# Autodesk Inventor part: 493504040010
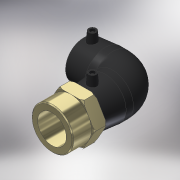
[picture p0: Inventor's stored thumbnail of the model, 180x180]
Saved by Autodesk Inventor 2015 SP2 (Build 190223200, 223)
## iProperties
Created: 2017-06
Part Number: 493504040010
Material: Generic
Description: PLASSON 90° ELBOW FEMALE TRANSITION 40-1''
Document SubType Name: Modeling
Designer: KIM
Mass: 218.635 g
Surface Area: 504.52 cm^2
Volume: 218.635 cm^3
Density: 1 g/cm^3
Appearance: Rubber - Black
Author: KIM
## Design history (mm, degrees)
derived "493504.ipt"
feature "Solid1::493504.ipt"
tag "TaggingFeature1"
body "Solid1"
other parameters: "d2" = 56, "d4" = 30.66667, "d5" = 50.4, "d8" = 168 deg, "d10" = 17.6, "d11" = 5.86667, "d29" = 47, "d30" = 15, "d31" = 50.6, "d34" = 5 deg, "d41" = 4, "d42" = 14, "d43" = 0, "d48" = 64, "d50" = 34, "d51" = 17.6, "d52" = 44, "d54" = 90 deg, "d58" = 44, "d59" = 0, "d61" = 90 deg, "d86" = 3, "d87" = 0, "d93" = 0.1, "d96" = 30.291, "d97" = 29, "d98" = 25, "d99" = 56, "d108" = 0, "d109" = 1.2, "d112" = 45 deg, "d113" = 45 deg, "d114" = 2, "L_" = 117, "L_1" = 44, "D_" = 29, "A_" = 47, "d_2" = 12, "L_2" = 25, "D_1" = 56, "Rp_" = 30.291
